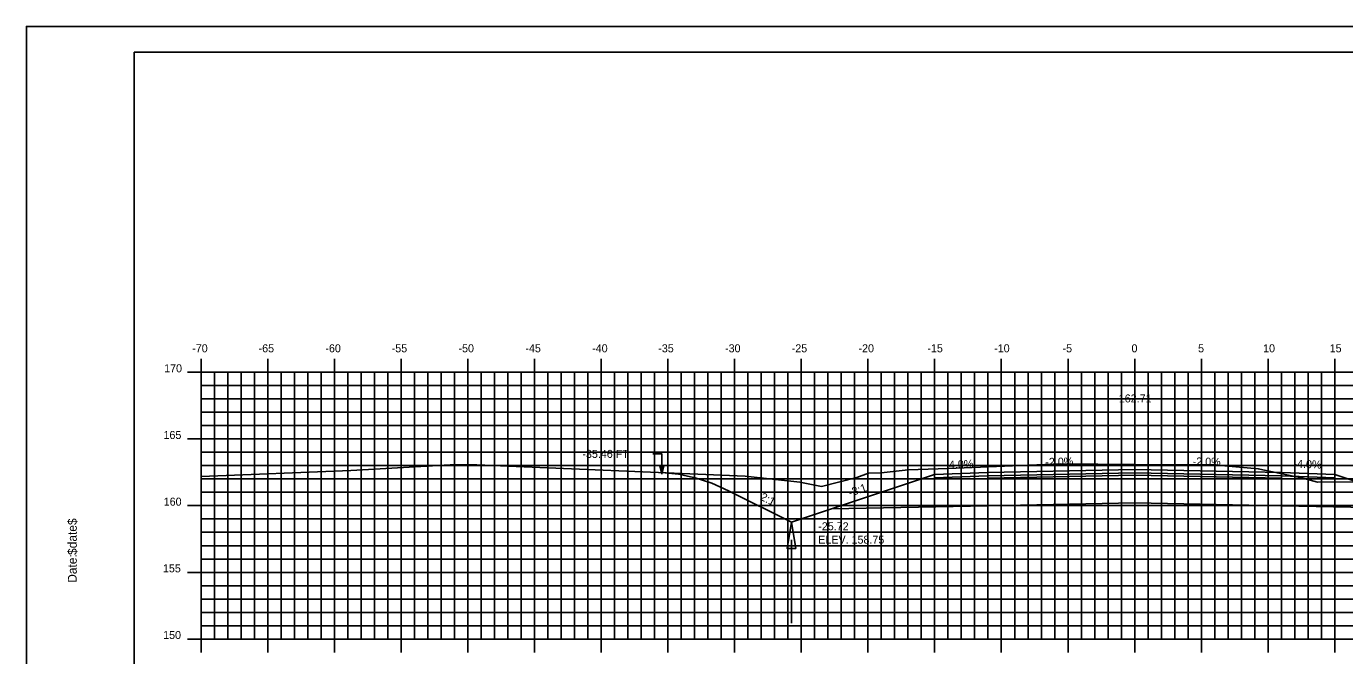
# Model space of a CAD drawing. Extents: x 1142976 to 1143146, y 608981 to 609091.
# Drawn here: x 1142976.5 to 1143075.3, y 609044.1 to 609091.3 of the extents above; entities that cross this region are included whole.
import ezdxf

# ---------------------------------------------------------------- set-up
doc = ezdxf.new("R2010")
doc.units = 0
for name, color, linetype in [('ANNOTATION', 7, 'Continuous'), ('BORDER', 7, 'Continuous'), ('D_Drainage_Ditch_Line', 7, 'Continuous'), ('D_Roadway_Centerline', 7, 'Continuous'), ('D_Roadway_Centerline_Text', 7, 'Continuous'), ('D_Roadway_Edge_Shoulder', 7, 'Continuous'), ('D_Roadway_Edge_TW', 7, 'Continuous'), ('D_Roadway_Pavement', 7, 'Continuous'), ('D_Roadway_SlopeLines', 7, 'Continuous'), ('D_Roadway_SubGrade', 7, 'Continuous'), ('D_Text_Standard', 7, 'Continuous'), ('H_V ANNOTATION', 7, 'Continuous'), ('MAJOR', 7, 'Continuous'), ('MINOR', 7, 'Continuous'), ('PLOT BOUNDARY', 7, 'Continuous'), ('S_Roadway_Centerline', 7, 'Continuous')]:
    doc.layers.add(name, color=color, linetype=linetype)

msp = doc.modelspace()

# ---------------------------------------------------------------- linework, layer by layer
msp.add_lwpolyline([(1143024.106, 609057.813), (1143025.356, 609057.688), (1143026.606, 609057.421), (1143027.856, 609057.01), (1143029.106, 609056.457), (1143033.842, 609054.089), (1143036.842, 609055.089), (1143044.566, 609057.664), (1143044.567, 609057.664), (1143048.567, 609057.824), (1143059.567, 609058.044), (1143070.567, 609057.824), (1143074.567, 609057.664), (1143082.29, 609055.089), (1143085.29, 609054.089), (1143088.668, 609055.778), (1143089.918, 609056.324), (1143091.168, 609056.71), (1143092.418, 609056.938), (1143093.668, 609057.008)])
at = {"layer": 'BORDER'}
msp.add_lwpolyline([(1142984.567, 608984.335), (1143144.567, 608984.335), (1143144.567, 609089.335), (1142984.567, 609089.335)], close=True, dxfattribs=at)
at = {"layer": 'D_Drainage_Ditch_Line'}
msp.add_line((1143033.842, 609052.777), (1143033.842, 609046.533), dxfattribs=at)
msp.add_lwpolyline([(1143034.17, 609052.121), (1143033.514, 609052.121), (1143033.842, 609054.089)], close=True, dxfattribs=at)
at = {"layer": 'D_Roadway_Edge_Shoulder'}
for points in [[(1143048.567, 609057.824), (1143044.567, 609057.664), (1143044.567, 609057.414), (1143048.567, 609057.574)], [(1143070.567, 609057.824), (1143074.567, 609057.664), (1143074.567, 609057.414), (1143070.567, 609057.574)]]:
    msp.add_lwpolyline(points, close=True, dxfattribs=at)
at = {"layer": 'D_Roadway_Edge_TW'}
msp.add_lwpolyline([(1143048.567, 609057.574), (1143048.567, 609057.824), (1143059.567, 609058.044), (1143070.567, 609057.824), (1143070.567, 609057.574), (1143059.567, 609057.794)], close=True, dxfattribs=at)
at = {"layer": 'D_Roadway_Pavement'}
msp.add_lwpolyline([(1143048.567, 609057.407), (1143048.567, 609057.574), (1143059.567, 609057.794), (1143070.567, 609057.574), (1143070.567, 609057.407), (1143059.567, 609057.627)], close=True, dxfattribs=at)
at = {"layer": 'D_Roadway_SlopeLines'}
for points in [[(1143033.842, 609054.089), (1143029.106, 609056.457), (1143027.856, 609057.01), (1143026.606, 609057.421), (1143025.356, 609057.688), (1143024.106, 609057.813)], [(1143036.842, 609055.089), (1143033.842, 609054.089)]]:
    msp.add_lwpolyline(points, dxfattribs=at)
at = {"layer": 'D_Roadway_SubGrade'}
for points in [[(1143048.567, 609057.407), (1143048.567, 609057.574), (1143044.567, 609057.414), (1143044.567, 609057.664), (1143044.566, 609057.664), (1143036.842, 609055.089), (1143048.567, 609055.324)], [(1143048.567, 609055.324), (1143048.567, 609057.407), (1143059.567, 609057.627), (1143070.567, 609057.407), (1143070.567, 609055.324), (1143059.567, 609055.544)], [(1143070.567, 609057.407), (1143070.567, 609057.574), (1143074.567, 609057.414), (1143074.567, 609057.664), (1143074.567, 609057.664), (1143082.29, 609055.089), (1143070.567, 609055.324)]]:
    msp.add_lwpolyline(points, close=True, dxfattribs=at)
at = {"layer": 'D_Text_Standard'}
msp.add_lwpolyline([(1143024.106, 609057.707), (1143024.123, 609059.217), (1143023.443, 609059.217)], dxfattribs=at)
msp.add_lwpolyline([(1143024.106, 609057.707), (1143023.967, 609058.291), (1143024.258, 609058.287)], close=True, dxfattribs=at)
at = {"layer": 'MAJOR'}
for p, q in [((1142989.567, 609066.337), (1142989.567, 609065.335)), ((1142994.567, 609066.337), (1142994.567, 609065.335)), ((1142999.567, 609066.337), (1142999.567, 609065.335)), ((1143004.567, 609066.337), (1143004.567, 609065.335)), ((1143009.567, 609066.337), (1143009.567, 609065.335)), ((1143014.567, 609066.337), (1143014.567, 609065.335)), ((1143019.567, 609066.337), (1143019.567, 609065.335)), ((1143024.567, 609066.337), (1143024.567, 609065.335)), ((1143029.567, 609066.337), (1143029.567, 609065.335)), ((1143034.567, 609066.337), (1143034.567, 609065.335)), ((1143039.567, 609066.337), (1143039.567, 609065.335)), ((1143044.567, 609066.337), (1143044.567, 609065.335)), ((1143049.567, 609066.337), (1143049.567, 609065.335)), ((1143054.567, 609066.337), (1143054.567, 609065.335)), ((1143059.567, 609066.337), (1143059.567, 609065.335)), ((1143064.567, 609066.337), (1143064.567, 609065.335)), ((1143069.567, 609066.337), (1143069.567, 609065.335)), ((1143074.567, 609066.337), (1143074.567, 609065.335)), ((1142988.565, 609065.335), (1142989.567, 609065.335)), ((1142989.567, 609065.335), (1143129.567, 609065.335)), ((1142989.567, 609045.335), (1142989.567, 609065.335)), ((1142989.567, 609045.335), (1142989.567, 609065.335)), ((1142989.567, 609065.335), (1143129.567, 609065.335)), ((1142994.567, 609045.335), (1142994.567, 609065.335)), ((1142999.567, 609045.335), (1142999.567, 609065.335)), ((1143004.567, 609045.335), (1143004.567, 609065.335)), ((1143009.567, 609045.335), (1143009.567, 609065.335)), ((1143014.567, 609045.335), (1143014.567, 609065.335)), ((1143019.567, 609045.335), (1143019.567, 609065.335)), ((1143024.567, 609045.335), (1143024.567, 609065.335)), ((1143029.567, 609045.335), (1143029.567, 609065.335)), ((1143034.567, 609045.335), (1143034.567, 609065.335)), ((1143039.567, 609045.335), (1143039.567, 609065.335)), ((1143044.567, 609045.335), (1143044.567, 609065.335)), ((1143049.567, 609045.335), (1143049.567, 609065.335)), ((1143054.567, 609045.335), (1143054.567, 609065.335)), ((1143059.567, 609045.335), (1143059.567, 609065.335)), ((1143064.567, 609045.335), (1143064.567, 609065.335)), ((1143069.567, 609045.335), (1143069.567, 609065.335)), ((1143074.567, 609045.335), (1143074.567, 609065.335)), ((1142988.565, 609060.335), (1142989.567, 609060.335)), ((1142989.567, 609060.335), (1143129.567, 609060.335)), ((1142988.565, 609055.335), (1142989.567, 609055.335)), ((1142989.567, 609055.335), (1143129.567, 609055.335)), ((1142988.565, 609050.335), (1142989.567, 609050.335)), ((1142989.567, 609050.335), (1143129.567, 609050.335)), ((1142988.565, 609045.335), (1142989.567, 609045.335)), ((1142989.567, 609045.335), (1143129.567, 609045.335)), ((1142989.567, 609045.335), (1143129.567, 609045.335)), ((1142989.567, 609044.333), (1142989.567, 609045.335)), ((1142994.567, 609044.333), (1142994.567, 609045.335)), ((1142999.567, 609044.333), (1142999.567, 609045.335)), ((1143004.567, 609044.333), (1143004.567, 609045.335)), ((1143009.567, 609044.333), (1143009.567, 609045.335)), ((1143014.567, 609044.333), (1143014.567, 609045.335)), ((1143019.567, 609044.333), (1143019.567, 609045.335)), ((1143024.567, 609044.333), (1143024.567, 609045.335)), ((1143029.567, 609044.333), (1143029.567, 609045.335)), ((1143034.567, 609044.333), (1143034.567, 609045.335)), ((1143039.567, 609044.333), (1143039.567, 609045.335)), ((1143044.567, 609044.333), (1143044.567, 609045.335)), ((1143049.567, 609044.333), (1143049.567, 609045.335)), ((1143054.567, 609044.333), (1143054.567, 609045.335)), ((1143059.567, 609044.333), (1143059.567, 609045.335)), ((1143064.567, 609044.333), (1143064.567, 609045.335)), ((1143069.567, 609044.333), (1143069.567, 609045.335)), ((1143074.567, 609044.333), (1143074.567, 609045.335))]:
    msp.add_line(p, q, dxfattribs=at)
at = {"layer": 'MINOR'}
for p, q in [((1142990.567, 609045.335), (1142990.567, 609065.335)), ((1142991.567, 609045.335), (1142991.567, 609065.335)), ((1142992.567, 609045.335), (1142992.567, 609065.335)), ((1142993.567, 609045.335), (1142993.567, 609065.335)), ((1142995.567, 609045.335), (1142995.567, 609065.335)), ((1142996.567, 609045.335), (1142996.567, 609065.335)), ((1142997.567, 609045.335), (1142997.567, 609065.335)), ((1142998.567, 609045.335), (1142998.567, 609065.335)), ((1143000.567, 609045.335), (1143000.567, 609065.335)), ((1143001.567, 609045.335), (1143001.567, 609065.335)), ((1143002.567, 609045.335), (1143002.567, 609065.335)), ((1143003.567, 609045.335), (1143003.567, 609065.335)), ((1143005.567, 609045.335), (1143005.567, 609065.335)), ((1143006.567, 609045.335), (1143006.567, 609065.335)), ((1143007.567, 609045.335), (1143007.567, 609065.335)), ((1143008.567, 609045.335), (1143008.567, 609065.335)), ((1143010.567, 609045.335), (1143010.567, 609065.335)), ((1143011.567, 609045.335), (1143011.567, 609065.335)), ((1143012.567, 609045.335), (1143012.567, 609065.335)), ((1143013.567, 609045.335), (1143013.567, 609065.335)), ((1143015.567, 609045.335), (1143015.567, 609065.335)), ((1143016.567, 609045.335), (1143016.567, 609065.335)), ((1143017.567, 609045.335), (1143017.567, 609065.335)), ((1143018.567, 609045.335), (1143018.567, 609065.335)), ((1143020.567, 609045.335), (1143020.567, 609065.335)), ((1143021.567, 609045.335), (1143021.567, 609065.335)), ((1143022.567, 609045.335), (1143022.567, 609065.335)), ((1143023.567, 609045.335), (1143023.567, 609065.335)), ((1143025.567, 609045.335), (1143025.567, 609065.335)), ((1143026.567, 609045.335), (1143026.567, 609065.335)), ((1143027.567, 609045.335), (1143027.567, 609065.335)), ((1143028.567, 609045.335), (1143028.567, 609065.335)), ((1143030.567, 609045.335), (1143030.567, 609065.335)), ((1143031.567, 609045.335), (1143031.567, 609065.335)), ((1143032.567, 609045.335), (1143032.567, 609065.335)), ((1143033.567, 609045.335), (1143033.567, 609065.335)), ((1143035.567, 609045.335), (1143035.567, 609065.335)), ((1143036.567, 609045.335), (1143036.567, 609065.335)), ((1143037.567, 609045.335), (1143037.567, 609065.335)), ((1143038.567, 609045.335), (1143038.567, 609065.335)), ((1143040.567, 609045.335), (1143040.567, 609065.335)), ((1143041.567, 609045.335), (1143041.567, 609065.335)), ((1143042.567, 609045.335), (1143042.567, 609065.335)), ((1143043.567, 609045.335), (1143043.567, 609065.335)), ((1143045.567, 609045.335), (1143045.567, 609065.335)), ((1143046.567, 609045.335), (1143046.567, 609065.335)), ((1143047.567, 609045.335), (1143047.567, 609065.335)), ((1143048.567, 609045.335), (1143048.567, 609065.335)), ((1143050.567, 609045.335), (1143050.567, 609065.335)), ((1143051.567, 609045.335), (1143051.567, 609065.335)), ((1143052.567, 609045.335), (1143052.567, 609065.335)), ((1143053.567, 609045.335), (1143053.567, 609065.335)), ((1143055.567, 609045.335), (1143055.567, 609065.335)), ((1143056.567, 609045.335), (1143056.567, 609065.335)), ((1143057.567, 609045.335), (1143057.567, 609065.335)), ((1143058.567, 609045.335), (1143058.567, 609065.335)), ((1143060.567, 609045.335), (1143060.567, 609065.335)), ((1143061.567, 609045.335), (1143061.567, 609065.335)), ((1143062.567, 609045.335), (1143062.567, 609065.335)), ((1143063.567, 609045.335), (1143063.567, 609065.335)), ((1143065.567, 609045.335), (1143065.567, 609065.335)), ((1143066.567, 609045.335), (1143066.567, 609065.335)), ((1143067.567, 609045.335), (1143067.567, 609065.335)), ((1143068.567, 609045.335), (1143068.567, 609065.335)), ((1143070.567, 609045.335), (1143070.567, 609065.335)), ((1143071.567, 609045.335), (1143071.567, 609065.335)), ((1143072.567, 609045.335), (1143072.567, 609065.335)), ((1143073.567, 609045.335), (1143073.567, 609065.335)), ((1142989.567, 609064.335), (1143129.567, 609064.335)), ((1142989.567, 609064.335), (1142990.569, 609064.335)), ((1142989.567, 609063.335), (1143129.567, 609063.335)), ((1142989.567, 609063.335), (1142990.569, 609063.335)), ((1142989.567, 609062.335), (1143129.567, 609062.335)), ((1142989.567, 609062.335), (1142990.569, 609062.335)), ((1142989.567, 609061.335), (1143129.567, 609061.335)), ((1142989.567, 609061.335), (1142990.569, 609061.335)), ((1142989.567, 609059.335), (1143129.567, 609059.335)), ((1142989.567, 609059.335), (1142990.569, 609059.335)), ((1142989.567, 609058.335), (1143129.567, 609058.335)), ((1142989.567, 609058.335), (1142990.569, 609058.335)), ((1142989.567, 609057.335), (1143129.567, 609057.335)), ((1142989.567, 609057.335), (1142990.569, 609057.335)), ((1142989.567, 609056.335), (1143129.567, 609056.335)), ((1142989.567, 609056.335), (1142990.569, 609056.335)), ((1142989.567, 609054.335), (1143129.567, 609054.335)), ((1142989.567, 609054.335), (1142990.569, 609054.335)), ((1142989.567, 609053.335), (1143129.567, 609053.335)), ((1142989.567, 609053.335), (1142990.569, 609053.335)), ((1142989.567, 609052.335), (1143129.567, 609052.335)), ((1142989.567, 609052.335), (1142990.569, 609052.335)), ((1142989.567, 609051.335), (1143129.567, 609051.335)), ((1142989.567, 609051.335), (1142990.569, 609051.335)), ((1142989.567, 609049.335), (1143129.567, 609049.335)), ((1142989.567, 609049.335), (1142990.569, 609049.335)), ((1142989.567, 609048.335), (1143129.567, 609048.335)), ((1142989.567, 609048.335), (1142990.569, 609048.335)), ((1142989.567, 609047.335), (1143129.567, 609047.335)), ((1142989.567, 609047.335), (1142990.569, 609047.335)), ((1142989.567, 609046.335), (1143129.567, 609046.335)), ((1142989.567, 609046.335), (1142990.569, 609046.335))]:
    msp.add_line(p, q, dxfattribs=at)
at = {"layer": 'PLOT BOUNDARY'}
msp.add_lwpolyline([(1142976.473, 608981.276), (1143146.473, 608981.276), (1143146.473, 609091.276), (1142976.473, 609091.276)], close=True, dxfattribs=at)
at = {"layer": 'S_Roadway_Centerline'}
msp.add_lwpolyline([(1142989.567, 609057.515), (1143000.793, 609057.983), (1143008.234, 609058.403), (1143010.248, 609058.4), (1143030.364, 609057.548), (1143034.453, 609057.089), (1143036.075, 609056.784), (1143038.74, 609057.457), (1143039.603, 609057.77), (1143040.548, 609057.805), (1143042.591, 609058.025), (1143045.569, 609058.133), (1143054.031, 609058.462), (1143062.329, 609058.395), (1143065.441, 609058.42), (1143066.331, 609058.333), (1143068.826, 609058.103), (1143072.162, 609057.402), (1143073.276, 609057.103), (1143079.308, 609057.124), (1143079.395, 609057.13), (1143080.178, 609057.118), (1143119.741, 609056.795), (1143129.567, 609056.713)], dxfattribs=at)

# ---------------------------------------------------------------- texts
at = {"layer": 'ANNOTATION'}
for s, rotation, p in [('-4.0%', 2.29061, (1143045.382, 609058.097)), ('-2.0%', 1.14576, (1143052.87, 609058.31)), ('-2.0%', 358.85424, (1143063.91, 609058.357)), ('-4.0%', 357.70939, (1143071.462, 609058.189)), ('2:1', 333.43495, (1143031.441, 609055.807)), ('-3:1', 18.43482, (1143038.221, 609056.003))]:
    msp.add_text(s, height=0.6, rotation=rotation, dxfattribs=at).set_placement(p)
at = {"layer": 'BORDER'}
for s, p in [('$date$', (1142980.252, 609051.64)), ('Date:', (1142980.252, 609049.552))]:
    msp.add_text(s, height=0.6696, rotation=90, dxfattribs=at).set_placement(p)
at = {"layer": 'D_Roadway_Centerline'}
for s, p in [('C', (1143059.561, 609058.044)), ('L', (1143059.567, 609058.036))]:
    msp.add_text(s, height=0.0146, dxfattribs=at).set_placement(p)
at = {"layer": 'D_Roadway_Centerline_Text'}
msp.add_text('162.71', height=0.6, dxfattribs=at).set_placement((1143058.373, 609063.076))
at = {"layer": 'D_Text_Standard'}
for s, p in [('-35.46 FT', (1143018.16, 609058.917)), ('-25.72', (1143035.842, 609053.489)), ('ELEV. 158.75', (1143035.842, 609052.487))]:
    msp.add_text(s, height=0.6, dxfattribs=at).set_placement(p)
at = {"layer": 'H_V ANNOTATION'}
for s, p in [('-70', (1142988.908, 609066.835)), ('-65', (1142993.884, 609066.835)), ('-60', (1142998.892, 609066.835)), ('-55', (1143003.863, 609066.835)), ('-50', (1143008.871, 609066.835)), ('-45', (1143013.884, 609066.835)), ('-40', (1143018.892, 609066.835)), ('-35', (1143023.847, 609066.835)), ('-30', (1143028.855, 609066.835)), ('-25', (1143033.852, 609066.835)), ('-20', (1143038.86, 609066.835)), ('-15', (1143044.023, 609066.835)), ('-10', (1143049.031, 609066.835)), ('-5', (1143054.157, 609066.835)), ('0', (1143059.326, 609066.835)), ('5', (1143064.318, 609066.835)), ('10', (1143069.192, 609066.835)), ('15', (1143074.184, 609066.835)), ('170', (1142986.803, 609065.335)), ('165', (1142986.755, 609060.335)), ('160', (1142986.771, 609055.335)), ('155', (1142986.712, 609050.335)), ('150', (1142986.728, 609045.335))]:
    msp.add_text(s, height=0.6, dxfattribs=at).set_placement(p)
at = {"layer": 'MAJOR'}
msp.add_text('-', height=0.006, dxfattribs=at).set_placement((1142989.562, 609045.335))
at = {"layer": 'S_Roadway_Centerline'}
for s, p in [('L', (1143054.022, 609058.455)), ('C', (1143054.026, 609058.462))]:
    msp.add_text(s, height=0.0146, dxfattribs=at).set_placement(p)

doc.saveas('drawing.dxf')
